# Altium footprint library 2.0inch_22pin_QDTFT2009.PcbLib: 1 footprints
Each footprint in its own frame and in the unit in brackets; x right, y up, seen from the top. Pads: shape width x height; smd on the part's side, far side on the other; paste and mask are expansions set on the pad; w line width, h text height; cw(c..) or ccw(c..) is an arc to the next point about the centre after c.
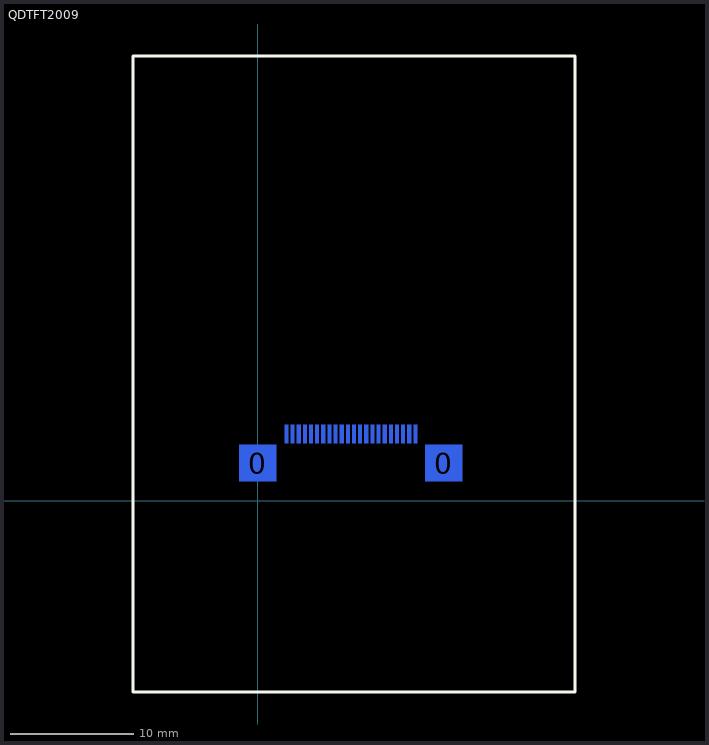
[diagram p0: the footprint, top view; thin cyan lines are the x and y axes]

## QDTFT2009 [mm] "2.0 TFT IPS"
pads (24):
  rect 3x3 smd far side: 0(0.023,3.07) 0(15.139,3.07)
  rect 0.3x1.5 smd far side: 1(2.345,5.44) 2(2.845,5.44) 3(3.345,5.44) 4(3.845,5.44) 5(4.345,5.44) 6(4.845,5.44) 7(5.345,5.44) 8(5.845,5.44) 9(6.345,5.44) 10(6.845,5.44) 11(7.345,5.44) 12(7.845,5.44) 13(8.345,5.44) 14(8.845,5.44) 15(9.345,5.44) 16(9.845,5.44) 17(10.345,5.44) 18(10.845,5.44) 19(11.345,5.44) 20(11.845,5.44) 21(12.345,5.44) 22(12.845,5.44)
Top Overlay:
  lines w0.254: -10.155,-15.58 25.845,-15.58 25.845,36.22 -10.155,36.22 -10.155,-15.58
Bottom Overlay:
  lines w0.2: -1.78,0.938 -1.78,4.291 ; -1.78,1.472 -1.78,-0.357 16.968,-0.357 16.968,1.345 ; -1.78,3.936 -1.78,5.282 1.598,5.282 1.598,6.857 13.59,6.857 13.59,5.186 14.011,5.186 16.968,5.186 16.968,4.771 16.968,3.809 ; 16.968,0.811 16.968,4.164
  text "1" at 0.85,5.525 h1.02
  text "22" at 15.901,5.485 h1.02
